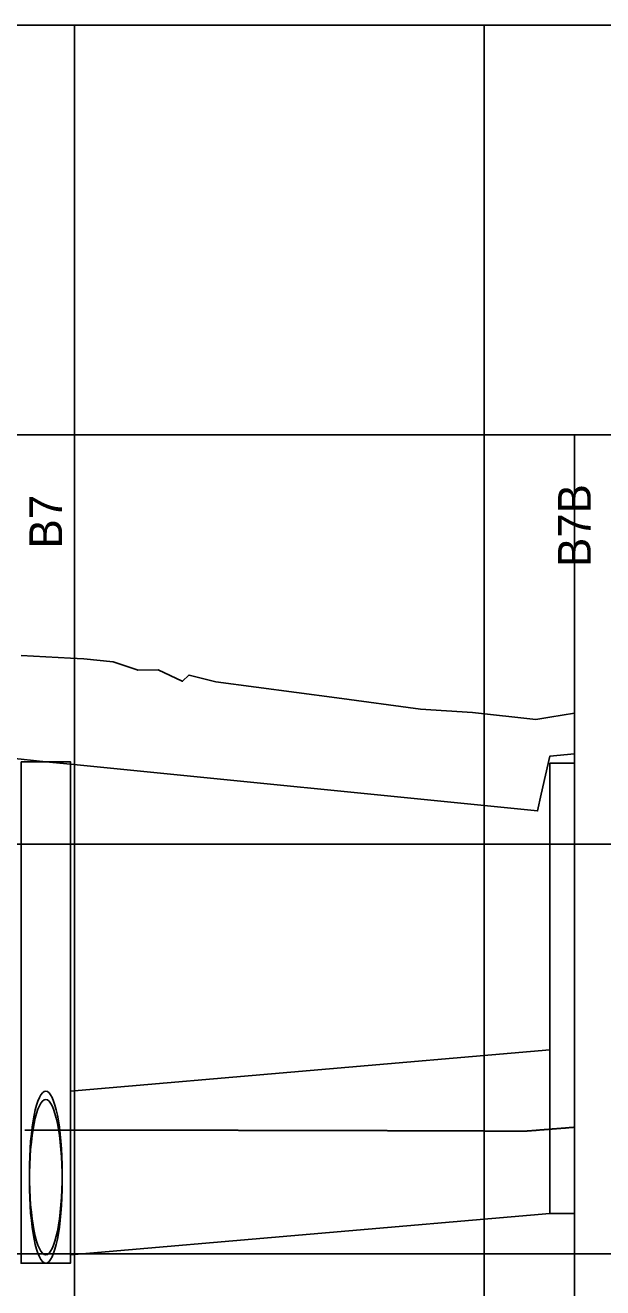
# Model space of a CAD drawing. Extents: x 2254979 to 2278074, y 13790855 to 13792793.
# Drawn here: x 2277996.4 to 2278031.6, y 13792714.2 to 13792791.3 of the extents above; entities that cross this region are included whole.
import ezdxf

# ---------------------------------------------------------------- set-up
doc = ezdxf.new("R2010")
doc.units = 0
for name, color, linetype in [('blank4', 7, 'Continuous'), ('BORD_grid_bottom_major_5int', 7, 'Continuous'), ('D_DRN_PROF_HGL', 7, 'Continuous'), ('D_PROF_1', 7, 'Continuous'), ('D_PROF_NOTES_1', 7, 'Continuous'), ('Drain_PipeInside', 7, 'Continuous'), ('E_Terrain', 7, 'Continuous'), ('Inlet', 7, 'Continuous'), ('z - Construction', 7, 'Continuous')]:
    doc.layers.add(name, color=color, linetype=linetype)

msp = doc.modelspace()

# ---------------------------------------------------------------- linework, layer by layer
at = {"layer": 'blank4'}
msp.add_lwpolyline([(2277949.404, 13792691.266), (2277949.404, 13792766.266), (2278029.904, 13792766.266), (2278029.904, 13792691.266)], close=True, dxfattribs=at)
at = {"layer": 'BORD_grid_bottom_major_5int'}
for p, q in [((2277749.404, 13792791.266), (2278074.404, 13792791.266)), ((2277999.404, 13792491.266), (2277999.404, 13792791.266)), ((2278024.404, 13792491.266), (2278024.404, 13792791.266)), ((2277749.404, 13792766.266), (2278074.404, 13792766.266)), ((2277749.404, 13792741.266), (2278074.404, 13792741.266)), ((2277749.404, 13792716.266), (2278074.404, 13792716.266))]:
    msp.add_line(p, q, dxfattribs=at)
at = {"layer": 'D_DRN_PROF_HGL'}
msp.add_line((2277997.654, 13792723.815), (2277997.654, 13792723.815), dxfattribs=at)
for points in [[(2277997.654, 13792723.815), (2277997.712, 13792723.815), (2277997.769, 13792723.815), (2277997.826, 13792723.815), (2277997.884, 13792723.815), (2277997.941, 13792723.815), (2277997.999, 13792723.815), (2277998.056, 13792723.815), (2277998.113, 13792723.815), (2277998.171, 13792723.815), (2277998.228, 13792723.815), (2277998.285, 13792723.815), (2277998.343, 13792723.815), (2277998.4, 13792723.815), (2277998.457, 13792723.815), (2277998.515, 13792723.815), (2277998.572, 13792723.815), (2277998.629, 13792723.815), (2277998.687, 13792723.815), (2277998.744, 13792723.814), (2277998.801, 13792723.814), (2277998.859, 13792723.814), (2277998.916, 13792723.814), (2277998.973, 13792723.814), (2277999.031, 13792723.814), (2277999.088, 13792723.814), (2277999.145, 13792723.814), (2277999.203, 13792723.814), (2277999.26, 13792723.814), (2277999.317, 13792723.814), (2277999.375, 13792723.814), (2277999.432, 13792723.814), (2277999.489, 13792723.814), (2277999.547, 13792723.814), (2277999.604, 13792723.814), (2277999.661, 13792723.814), (2277999.719, 13792723.814), (2277999.776, 13792723.814), (2277999.833, 13792723.813), (2277999.89, 13792723.813), (2277999.948, 13792723.813), (2278000.005, 13792723.813), (2278000.062, 13792723.813), (2278000.12, 13792723.813), (2278000.177, 13792723.813), (2278000.234, 13792723.813), (2278000.291, 13792723.813), (2278000.349, 13792723.813), (2278000.406, 13792723.813), (2278000.463, 13792723.813), (2278000.521, 13792723.813), (2278000.578, 13792723.813), (2278000.635, 13792723.813), (2278000.692, 13792723.813), (2278000.75, 13792723.813), (2278000.807, 13792723.813), (2278000.864, 13792723.812), (2278000.921, 13792723.812), (2278000.979, 13792723.812), (2278001.036, 13792723.812), (2278001.093, 13792723.812), (2278001.15, 13792723.812), (2278001.208, 13792723.812), (2278001.265, 13792723.812), (2278001.322, 13792723.812), (2278001.379, 13792723.812), (2278001.437, 13792723.812), (2278001.494, 13792723.812), (2278001.551, 13792723.812), (2278001.608, 13792723.812), (2278001.666, 13792723.812), (2278001.723, 13792723.812), (2278001.78, 13792723.812), (2278001.837, 13792723.811), (2278001.894, 13792723.811), (2278001.952, 13792723.811), (2278002.009, 13792723.811), (2278002.066, 13792723.811), (2278002.123, 13792723.811), (2278002.181, 13792723.811), (2278002.238, 13792723.811), (2278002.295, 13792723.811), (2278002.352, 13792723.811), (2278002.409, 13792723.811), (2278002.467, 13792723.811), (2278002.524, 13792723.811), (2278002.581, 13792723.811), (2278002.638, 13792723.811), (2278002.695, 13792723.811), (2278002.752, 13792723.811), (2278002.81, 13792723.81), (2278002.867, 13792723.81), (2278002.924, 13792723.81), (2278002.981, 13792723.81), (2278003.038, 13792723.81), (2278003.096, 13792723.81), (2278003.153, 13792723.81), (2278003.21, 13792723.81), (2278003.267, 13792723.81), (2278003.324, 13792723.81), (2278003.381, 13792723.81), (2278003.438, 13792723.81), (2278003.496, 13792723.81), (2278003.553, 13792723.81), (2278003.61, 13792723.81), (2278003.667, 13792723.809), (2278003.724, 13792723.809), (2278003.781, 13792723.809), (2278003.839, 13792723.809), (2278003.896, 13792723.809), (2278003.953, 13792723.809), (2278004.01, 13792723.809), (2278004.067, 13792723.809), (2278004.124, 13792723.809), (2278004.181, 13792723.809), (2278004.238, 13792723.809), (2278004.296, 13792723.809), (2278004.353, 13792723.809), (2278004.41, 13792723.809), (2278004.467, 13792723.808), (2278004.524, 13792723.808), (2278004.581, 13792723.808), (2278004.638, 13792723.808), (2278004.695, 13792723.808), (2278004.752, 13792723.808), (2278004.809, 13792723.808), (2278004.867, 13792723.808), (2278004.924, 13792723.808), (2278004.981, 13792723.808), (2278005.038, 13792723.808), (2278005.095, 13792723.808), (2278005.152, 13792723.808), (2278005.209, 13792723.808), (2278005.266, 13792723.807), (2278005.323, 13792723.807), (2278005.38, 13792723.807), (2278005.437, 13792723.807), (2278005.494, 13792723.807), (2278005.551, 13792723.807), (2278005.608, 13792723.807), (2278005.665, 13792723.807), (2278005.723, 13792723.807), (2278005.78, 13792723.807), (2278005.837, 13792723.807), (2278005.894, 13792723.807), (2278005.951, 13792723.807), (2278006.008, 13792723.807), (2278006.065, 13792723.806), (2278006.122, 13792723.806), (2278006.179, 13792723.806), (2278006.236, 13792723.806), (2278006.293, 13792723.806), (2278006.35, 13792723.806), (2278006.407, 13792723.806), (2278006.464, 13792723.806), (2278006.521, 13792723.806), (2278006.578, 13792723.806), (2278006.635, 13792723.806), (2278006.692, 13792723.806), (2278006.749, 13792723.805), (2278006.806, 13792723.805), (2278006.863, 13792723.805), (2278006.92, 13792723.805), (2278006.977, 13792723.805), (2278007.034, 13792723.805), (2278007.091, 13792723.805), (2278007.148, 13792723.805), (2278007.205, 13792723.805), (2278007.262, 13792723.805), (2278007.319, 13792723.805), (2278007.376, 13792723.805), (2278007.433, 13792723.805), (2278007.49, 13792723.804), (2278007.547, 13792723.804), (2278007.603, 13792723.804), (2278007.66, 13792723.804), (2278007.717, 13792723.804), (2278007.774, 13792723.804), (2278007.831, 13792723.804), (2278007.888, 13792723.804), (2278007.945, 13792723.804), (2278008.002, 13792723.804), (2278008.059, 13792723.804), (2278008.116, 13792723.803), (2278008.173, 13792723.803), (2278008.23, 13792723.803), (2278008.287, 13792723.803), (2278008.344, 13792723.803), (2278008.4, 13792723.803), (2278008.457, 13792723.803), (2278008.514, 13792723.803), (2278008.571, 13792723.803), (2278008.628, 13792723.803), (2278008.685, 13792723.803), (2278008.742, 13792723.803), (2278008.799, 13792723.802), (2278008.856, 13792723.802), (2278008.912, 13792723.802), (2278008.969, 13792723.802), (2278009.026, 13792723.802), (2278009.083, 13792723.802), (2278009.14, 13792723.802), (2278009.197, 13792723.802), (2278009.254, 13792723.802), (2278009.31, 13792723.802), (2278009.367, 13792723.802), (2278009.424, 13792723.801), (2278009.481, 13792723.801), (2278009.538, 13792723.801), (2278009.595, 13792723.801), (2278009.651, 13792723.801), (2278009.708, 13792723.801), (2278009.765, 13792723.801), (2278009.822, 13792723.801), (2278009.879, 13792723.801), (2278009.936, 13792723.801), (2278009.992, 13792723.8), (2278010.049, 13792723.8), (2278010.106, 13792723.8), (2278010.163, 13792723.8), (2278010.219, 13792723.8), (2278010.276, 13792723.8), (2278010.333, 13792723.8), (2278010.39, 13792723.8), (2278010.447, 13792723.8), (2278010.503, 13792723.8), (2278010.56, 13792723.799), (2278010.617, 13792723.799), (2278010.674, 13792723.799), (2278010.73, 13792723.799), (2278010.787, 13792723.799), (2278010.844, 13792723.799), (2278010.901, 13792723.799), (2278010.957, 13792723.799), (2278011.014, 13792723.799), (2278011.071, 13792723.799), (2278011.128, 13792723.798), (2278011.184, 13792723.798), (2278011.241, 13792723.798), (2278011.298, 13792723.798), (2278011.354, 13792723.798), (2278011.411, 13792723.798), (2278011.468, 13792723.798), (2278011.525, 13792723.798), (2278011.581, 13792723.798), (2278011.638, 13792723.798), (2278011.695, 13792723.797), (2278011.751, 13792723.797), (2278011.808, 13792723.797), (2278011.865, 13792723.797), (2278011.921, 13792723.797), (2278011.978, 13792723.797), (2278012.035, 13792723.797), (2278012.091, 13792723.797), (2278012.148, 13792723.797), (2278012.205, 13792723.796), (2278012.261, 13792723.796), (2278012.318, 13792723.796), (2278012.375, 13792723.796), (2278012.431, 13792723.796), (2278012.488, 13792723.796), (2278012.545, 13792723.796), (2278012.601, 13792723.796), (2278012.658, 13792723.796), (2278012.714, 13792723.795), (2278012.771, 13792723.795), (2278012.828, 13792723.795), (2278012.884, 13792723.795), (2278012.941, 13792723.795), (2278012.997, 13792723.795), (2278013.054, 13792723.795), (2278013.111, 13792723.795), (2278013.167, 13792723.795), (2278013.224, 13792723.794), (2278013.28, 13792723.794), (2278013.337, 13792723.794), (2278013.393, 13792723.794), (2278013.45, 13792723.794), (2278013.506, 13792723.794), (2278013.563, 13792723.794), (2278013.62, 13792723.794), (2278013.676, 13792723.793), (2278013.733, 13792723.793), (2278013.789, 13792723.793), (2278013.846, 13792723.793), (2278013.902, 13792723.793), (2278013.959, 13792723.793), (2278014.015, 13792723.793), (2278014.072, 13792723.793), (2278014.128, 13792723.793), (2278014.185, 13792723.792), (2278014.241, 13792723.792), (2278014.298, 13792723.792), (2278014.354, 13792723.792), (2278014.411, 13792723.792), (2278014.467, 13792723.792), (2278014.524, 13792723.792), (2278014.58, 13792723.792), (2278014.636, 13792723.791), (2278014.693, 13792723.791), (2278014.749, 13792723.791), (2278014.806, 13792723.791), (2278014.862, 13792723.791), (2278014.919, 13792723.791), (2278014.975, 13792723.791), (2278015.031, 13792723.79), (2278015.088, 13792723.79), (2278015.144, 13792723.79), (2278015.201, 13792723.79), (2278015.257, 13792723.79), (2278015.313, 13792723.79), (2278015.37, 13792723.79), (2278015.426, 13792723.79), (2278015.483, 13792723.789), (2278015.539, 13792723.789), (2278015.595, 13792723.789), (2278015.652, 13792723.789), (2278015.708, 13792723.789), (2278015.764, 13792723.789), (2278015.821, 13792723.789), (2278015.877, 13792723.788), (2278015.933, 13792723.788), (2278015.99, 13792723.788), (2278016.046, 13792723.788), (2278016.102, 13792723.788), (2278016.159, 13792723.788), (2278016.215, 13792723.788), (2278016.271, 13792723.788), (2278016.328, 13792723.787), (2278016.384, 13792723.787), (2278016.44, 13792723.787), (2278016.496, 13792723.787), (2278016.553, 13792723.787), (2278016.609, 13792723.787), (2278016.665, 13792723.787), (2278016.721, 13792723.786), (2278016.778, 13792723.786), (2278016.834, 13792723.786), (2278016.89, 13792723.786), (2278016.946, 13792723.786), (2278017.003, 13792723.786), (2278017.059, 13792723.785), (2278017.115, 13792723.785), (2278017.171, 13792723.785), (2278017.227, 13792723.785), (2278017.284, 13792723.785), (2278017.34, 13792723.785), (2278017.396, 13792723.785), (2278017.452, 13792723.784), (2278017.508, 13792723.784), (2278017.565, 13792723.784), (2278017.621, 13792723.784), (2278017.677, 13792723.784), (2278017.733, 13792723.784), (2278017.789, 13792723.784), (2278017.845, 13792723.783), (2278017.901, 13792723.783), (2278017.958, 13792723.783), (2278018.014, 13792723.783), (2278018.07, 13792723.783), (2278018.126, 13792723.783), (2278018.182, 13792723.782), (2278018.238, 13792723.782), (2278018.294, 13792723.782), (2278018.35, 13792723.782), (2278018.406, 13792723.782), (2278018.462, 13792723.782), (2278018.518, 13792723.781), (2278018.574, 13792723.781), (2278018.63, 13792723.781), (2278018.687, 13792723.781), (2278018.743, 13792723.781), (2278018.799, 13792723.781), (2278018.855, 13792723.781), (2278018.911, 13792723.78), (2278018.967, 13792723.78), (2278019.023, 13792723.78), (2278019.079, 13792723.78), (2278019.135, 13792723.78), (2278019.191, 13792723.78), (2278019.246, 13792723.779), (2278019.302, 13792723.779), (2278019.358, 13792723.779), (2278019.414, 13792723.779), (2278019.47, 13792723.779), (2278019.526, 13792723.778), (2278019.582, 13792723.778), (2278019.638, 13792723.778), (2278019.694, 13792723.778), (2278019.75, 13792723.778), (2278019.806, 13792723.778), (2278019.862, 13792723.777), (2278019.918, 13792723.777), (2278019.973, 13792723.777), (2278020.029, 13792723.777), (2278020.085, 13792723.777), (2278020.141, 13792723.777), (2278020.197, 13792723.776), (2278020.253, 13792723.776), (2278020.308, 13792723.776), (2278020.364, 13792723.776), (2278020.42, 13792723.776), (2278020.476, 13792723.775), (2278020.532, 13792723.775), (2278020.588, 13792723.775), (2278020.643, 13792723.775), (2278020.699, 13792723.775), (2278020.755, 13792723.775), (2278020.811, 13792723.774), (2278020.866, 13792723.774), (2278020.922, 13792723.774), (2278020.978, 13792723.774), (2278021.034, 13792723.774), (2278021.089, 13792723.773), (2278021.145, 13792723.773), (2278021.201, 13792723.773), (2278021.256, 13792723.773), (2278021.312, 13792723.773), (2278021.368, 13792723.772), (2278021.423, 13792723.772), (2278021.479, 13792723.772), (2278021.535, 13792723.772), (2278021.59, 13792723.772), (2278021.646, 13792723.771), (2278021.702, 13792723.771), (2278021.757, 13792723.771), (2278021.813, 13792723.771), (2278021.868, 13792723.771), (2278021.924, 13792723.77), (2278021.98, 13792723.77), (2278022.035, 13792723.77), (2278022.091, 13792723.77), (2278022.146, 13792723.77), (2278022.202, 13792723.769), (2278022.257, 13792723.769), (2278022.313, 13792723.769), (2278022.369, 13792723.769), (2278022.424, 13792723.769), (2278022.48, 13792723.768), (2278022.535, 13792723.768), (2278022.591, 13792723.768), (2278022.646, 13792723.768), (2278022.701, 13792723.768), (2278022.757, 13792723.767), (2278022.812, 13792723.767), (2278022.868, 13792723.767), (2278022.923, 13792723.767), (2278022.979, 13792723.767), (2278023.034, 13792723.766), (2278023.089, 13792723.766), (2278023.145, 13792723.766), (2278023.2, 13792723.766), (2278023.256, 13792723.765), (2278023.311, 13792723.765), (2278023.366, 13792723.765), (2278023.422, 13792723.765), (2278023.477, 13792723.765), (2278023.532, 13792723.764), (2278023.588, 13792723.764), (2278023.643, 13792723.764), (2278023.698, 13792723.764), (2278023.754, 13792723.763), (2278023.809, 13792723.763), (2278023.864, 13792723.763), (2278023.919, 13792723.763), (2278023.975, 13792723.762), (2278024.03, 13792723.762), (2278024.085, 13792723.762), (2278024.14, 13792723.762), (2278024.196, 13792723.762), (2278024.251, 13792723.761), (2278024.306, 13792723.761), (2278024.361, 13792723.761), (2278024.416, 13792723.761), (2278024.471, 13792723.76), (2278024.527, 13792723.76), (2278024.582, 13792723.76), (2278024.637, 13792723.76), (2278024.692, 13792723.759), (2278024.747, 13792723.759), (2278024.802, 13792723.759), (2278024.857, 13792723.759), (2278024.912, 13792723.758), (2278024.967, 13792723.758), (2278025.022, 13792723.758), (2278025.077, 13792723.758), (2278025.132, 13792723.757), (2278025.187, 13792723.757), (2278025.242, 13792723.757), (2278025.297, 13792723.757), (2278025.352, 13792723.756), (2278025.407, 13792723.756), (2278025.462, 13792723.756), (2278025.517, 13792723.756), (2278025.572, 13792723.755), (2278025.627, 13792723.755), (2278025.682, 13792723.755), (2278025.737, 13792723.755), (2278025.792, 13792723.754), (2278025.847, 13792723.754), (2278025.902, 13792723.754), (2278025.956, 13792723.754), (2278026.011, 13792723.753), (2278026.066, 13792723.753), (2278026.121, 13792723.753), (2278026.176, 13792723.753), (2278026.23, 13792723.752), (2278026.285, 13792723.752), (2278026.34, 13792723.752), (2278026.395, 13792723.751), (2278026.449, 13792723.751), (2278026.504, 13792723.751), (2278026.559, 13792723.751), (2278026.614, 13792723.75), (2278026.668, 13792723.75), (2278026.723, 13792723.75), (2278026.778, 13792723.749), (2278026.832, 13792723.749), (2278026.887, 13792723.749), (2278026.942, 13792723.752), (2278026.996, 13792723.756), (2278027.051, 13792723.761), (2278027.105, 13792723.765), (2278027.16, 13792723.77), (2278027.214, 13792723.774), (2278027.269, 13792723.778), (2278027.323, 13792723.783), (2278027.378, 13792723.787), (2278027.433, 13792723.792), (2278027.487, 13792723.796), (2278027.541, 13792723.8), (2278027.596, 13792723.805), (2278027.65, 13792723.809), (2278027.705, 13792723.814), (2278027.759, 13792723.818), (2278027.814, 13792723.822), (2278027.868, 13792723.827), (2278027.922, 13792723.831), (2278027.977, 13792723.836), (2278028.031, 13792723.84), (2278028.085, 13792723.844), (2278028.14, 13792723.849), (2278028.194, 13792723.853), (2278028.248, 13792723.857), (2278028.303, 13792723.862), (2278028.357, 13792723.866), (2278028.411, 13792723.871), (2278028.465, 13792723.875), (2278028.52, 13792723.879), (2278028.574, 13792723.884), (2278028.628, 13792723.888), (2278028.682, 13792723.892), (2278028.736, 13792723.897), (2278028.79, 13792723.901), (2278028.844, 13792723.905), (2278028.899, 13792723.91), (2278028.953, 13792723.914), (2278029.007, 13792723.918), (2278029.061, 13792723.923), (2278029.115, 13792723.927), (2278029.169, 13792723.931), (2278029.223, 13792723.936), (2278029.277, 13792723.94), (2278029.331, 13792723.944), (2278029.385, 13792723.949), (2278029.439, 13792723.953), (2278029.493, 13792723.957), (2278029.547, 13792723.962), (2278029.6, 13792723.966), (2278029.654, 13792723.97), (2278029.708, 13792723.974), (2278029.762, 13792723.979), (2278029.816, 13792723.983), (2278029.87, 13792723.987), (2278029.904, 13792723.988), (2278029.904, 13792724.399)], [(2277996.381, 13792723.815), (2277996.487, 13792723.815), (2277996.593, 13792723.815), (2277996.699, 13792723.815), (2277996.805, 13792723.815), (2277996.911, 13792723.815), (2277997.018, 13792723.815), (2277997.124, 13792723.815), (2277997.23, 13792723.815), (2277997.336, 13792723.815), (2277997.442, 13792723.815), (2277997.548, 13792723.815), (2277997.654, 13792723.815)]]:
    msp.add_lwpolyline(points, dxfattribs=at)
at = {"layer": 'D_PROF_1'}
msp.add_lwpolyline([(2277949.404, 13792746.385), (2277950.904, 13792746.235), (2277950.904, 13792746.235), (2277950.904, 13792746.235), (2277951.425, 13792743.342), (2277951.654, 13792742.069), (2277991.654, 13792746.902), (2277996.154, 13792746.452), (2277996.154, 13792746.452), (2277997.654, 13792746.302), (2277997.654, 13792746.302), (2277999.154, 13792746.152), (2277999.154, 13792746.152), (2278027.654, 13792743.302), (2278027.884, 13792744.32), (2278028.404, 13792746.635), (2278028.404, 13792746.635), (2278029.904, 13792746.785)], dxfattribs=at)
at = {"layer": 'Drain_PipeInside'}
for p, q in [((2277999.154, 13792726.191), (2278028.404, 13792728.716)), ((2277999.154, 13792716.191), (2278028.404, 13792718.716))]:
    msp.add_line(p, q, dxfattribs=at)
for centre in [(2277997.654, 13792721.191), (2277997.654, 13792720.691)]:
    msp.add_ellipse(centre, major_axis=(0, 5), ratio=0.2, dxfattribs=at)
at = {"layer": 'E_Terrain'}
msp.add_lwpolyline([(2277996.154, 13792752.781), (2277997.654, 13792752.704), (2277997.654, 13792752.704), (2277999.154, 13792752.627), (2277999.154, 13792752.627), (2277999.987, 13792752.584), (2278001.771, 13792752.4), (2278003.222, 13792751.922), (2278003.266, 13792751.899), (2278004.514, 13792751.909), (2278005.973, 13792751.221), (2278005.974, 13792751.219), (2278005.993, 13792751.216), (2278005.997, 13792751.215), (2278006.391, 13792751.594), (2278006.4, 13792751.592), (2278008.032, 13792751.187), (2278015.407, 13792750.202), (2278020.505, 13792749.517), (2278023.694, 13792749.302), (2278027.541, 13792748.887), (2278028.404, 13792749.025), (2278028.404, 13792749.025), (2278029.904, 13792749.264)], dxfattribs=at)
at = {"layer": 'Inlet'}
for points in [[(2277996.154, 13792746.302), (2277999.154, 13792746.302), (2277999.154, 13792715.691), (2277996.154, 13792715.691)], [(2278028.404, 13792746.219), (2278029.904, 13792746.219), (2278029.904, 13792718.716), (2278028.404, 13792718.716)]]:
    msp.add_lwpolyline(points, close=True, dxfattribs=at)
at = {"layer": 'z - Construction'}
for p, q in [((2277949.404, 13792741.266), (2278029.904, 13792741.266)), ((2277949.404, 13792716.266), (2278029.904, 13792716.266))]:
    msp.add_line(p, q, dxfattribs=at)

# ---------------------------------------------------------------- texts
at = {"layer": 'D_PROF_NOTES_1'}
for s, p in [('B7', (2277998.654, 13792759.326)), ('B7B', (2278030.904, 13792758.196))]:
    msp.add_text(s, height=2, rotation=90, dxfattribs=at).set_placement(p)

doc.saveas('drawing.dxf')
